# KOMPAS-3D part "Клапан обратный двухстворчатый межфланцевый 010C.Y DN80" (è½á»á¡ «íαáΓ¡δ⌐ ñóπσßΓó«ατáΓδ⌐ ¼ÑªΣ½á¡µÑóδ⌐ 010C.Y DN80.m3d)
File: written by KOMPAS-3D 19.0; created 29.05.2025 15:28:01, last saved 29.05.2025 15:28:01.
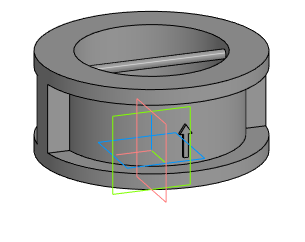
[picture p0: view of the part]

Document properties: Полное имя файла: E:\Dendor Работа Сачек\3D для проекитирвщиков\5.2 Тип 010C, 010C.Y Клапан обратный двухстворчатый межфланцевый\stp_Клапан обратный двухстворчатый межфланцевый 010C.Y\Клапан обратный двухстворчатый межфланцевый 010C.Y DN80.m3d

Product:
- Part/product: Клапан обратный двухстворчатый межфланцевый 010C.Y DN80

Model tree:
1. Операция без истории:1  (labels: Клапан обратный двухстворчатый межфланцевый 010C.Y DN80)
